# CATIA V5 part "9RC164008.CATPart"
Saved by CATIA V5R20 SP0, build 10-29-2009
Part number: 9RC164008
Revision: ANY
Definition: UNKNOWN
Nomenclature: 9RC164008
Source: Unknown
Bounding box of the stored display mesh (mm): x -32 to 8, y -8 to 8, z -2.85 to 2.85
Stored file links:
  C:\Users\Utente\Desktop\IO LAVORO\3D X SITO CF\CUMSA\3D files RC\RC 164008\9RC164008.CATPart
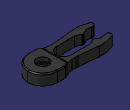
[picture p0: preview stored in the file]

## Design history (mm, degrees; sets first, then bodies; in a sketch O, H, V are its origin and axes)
Body1 "Chaflán1" (main body)
  Solid1: solid without history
